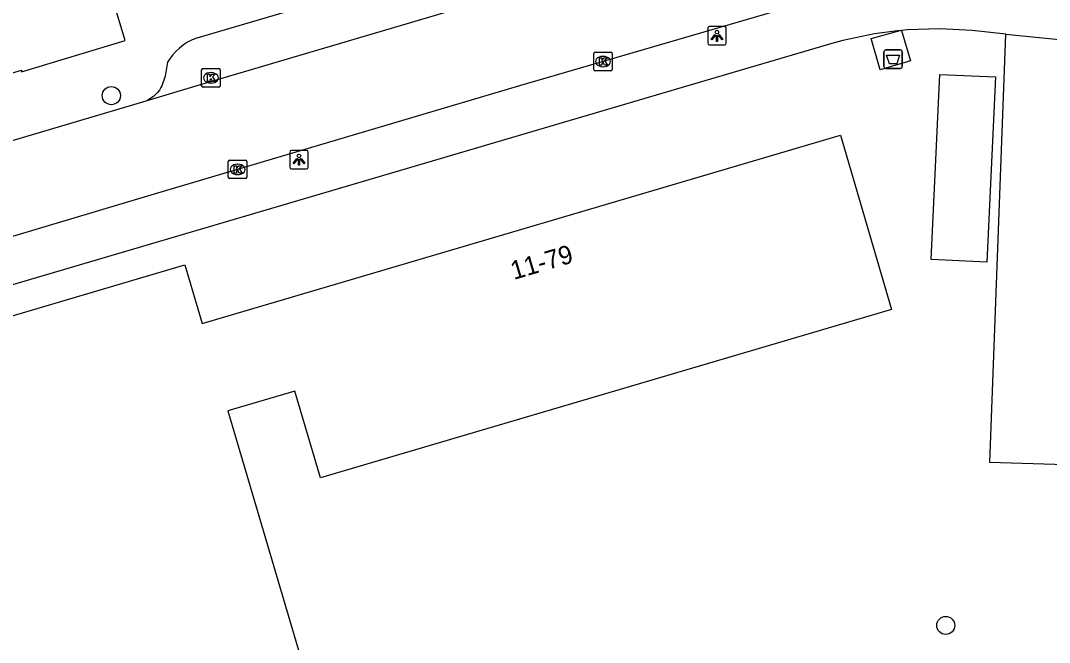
# Model space of a CAD drawing. Extents: x 161253 to 161848, y 384872 to 385383.
# Drawn here: x 161534.9 to 161590.4, y 384970 to 385003.5 of the extents above; entities that cross this region are included whole.
import ezdxf

# ---------------------------------------------------------------- set-up
doc = ezdxf.new("R2010")
doc.units = 0
for name, color, linetype in [('IMGEO_Afval_apart_plaats', 7, 'Continuous'), ('IMGEO_Boom', 7, 'Continuous'), ('IMGEO_Groenvoorziening', 7, 'Continuous'), ('IMGEO_Kolk', 7, 'Continuous'), ('IMGEO_Lichtpunt', 7, 'Continuous'), ('IMGEO_Pand', 7, 'Continuous'), ('IMGEO_Pand_nummerreeks', 7, 'Continuous'), ('IMGEO_Rijbaan_lokaal_open', 7, 'Continuous'), ('IMGEO_Voetpad_gesloten', 7, 'Continuous'), ('IMGEO_Voetpad_open', 7, 'Continuous')]:
    doc.layers.add(name, color=color, linetype=linetype)

msp = doc.modelspace()

# ---------------------------------------------------------------- linework, layer by layer
at = {"layer": 'IMGEO_Afval_apart_plaats'}
for p, q in [((161581.486, 385001.045), (161581.486, 385001.845)), ((161581.486, 385001.845), (161581.486, 385001.045)), ((161581.586, 385001.945), (161582.376, 385001.945)), ((161582.376, 385001.945), (161581.586, 385001.945)), ((161582.476, 385001.845), (161582.476, 385001.045)), ((161582.476, 385001.045), (161582.476, 385001.845)), ((161582.376, 385000.945), (161581.586, 385000.945)), ((161581.586, 385000.945), (161582.376, 385000.945))]:
    msp.add_line(p, q, dxfattribs=at)
msp.add_lwpolyline([(161581.629, 385001.659), (161582.333, 385001.659), (161582.184, 385001.189), (161581.778, 385001.189), (161581.629, 385001.659)], dxfattribs=at)
for centre, start, end in [((161581.586, 385001.845), 90, 180), ((161581.586, 385001.845), 90, 180), ((161582.376, 385001.845), 0, 90), ((161582.376, 385001.845), 360, 90), ((161581.586, 385001.045), 180, 270), ((161581.586, 385001.045), 180, 270), ((161582.376, 385001.045), 270, 0), ((161582.376, 385001.045), 270, 0)]:
    msp.add_arc(centre, 0.1, start, end, dxfattribs=at)
at = {"layer": 'IMGEO_Boom'}
for centre in [(161539.785, 384999.476), (161584.823, 384970.871)]:
    msp.add_circle(centre, 0.489, dxfattribs=at)
at = {"layer": 'IMGEO_Groenvoorziening'}
msp.add_lwpolyline([(161592.462, 384979.511), (161587.199, 384979.67), (161588.066, 385002.802)], dxfattribs=at)
at = {"layer": 'IMGEO_Kolk'}
for p, q in [((161565.894, 385001.819), (161566.746, 385001.819)), ((161565.819, 385000.893), (161565.819, 385001.745)), ((161566.307, 385001.599), (161566.332, 385001.599)), ((161566.82, 385001.745), (161566.82, 385000.893)), ((161544.659, 385000.012), (161544.659, 385000.864)), ((161544.734, 385000.938), (161545.586, 385000.938)), ((161545.147, 385000.718), (161545.172, 385000.718)), ((161545.66, 385000.864), (161545.66, 385000.012)), ((161566.746, 385000.819), (161565.894, 385000.819)), ((161566.33, 385001.039), (161566.305, 385001.039)), ((161545.17, 385000.158), (161545.145, 385000.158)), ((161545.586, 384999.938), (161544.734, 384999.938)), ((161546.099, 384995.069), (161546.099, 384995.921)), ((161546.174, 384995.995), (161547.026, 384995.995)), ((161546.587, 384995.775), (161546.612, 384995.775)), ((161547.1, 384995.921), (161547.1, 384995.069)), ((161546.61, 384995.215), (161546.585, 384995.215)), ((161547.026, 384994.995), (161546.174, 384994.995))]:
    msp.add_line(p, q, dxfattribs=at)
for points in [[(161565.894, 385001.819), (161566.746, 385001.819)], [(161565.819, 385000.893), (161565.819, 385001.745)], [(161566.14, 385001.519), (161566.263, 385001.519), (161566.263, 385001.368), (161566.393, 385001.519), (161566.557, 385001.519), (161566.411, 385001.368), (161566.564, 385001.119), (161566.412, 385001.119), (161566.327, 385001.283), (161566.263, 385001.216), (161566.263, 385001.119), (161566.14, 385001.119), (161566.14, 385001.519)], [(161566.82, 385001.745), (161566.82, 385000.893)], [(161544.659, 385000.012), (161544.659, 385000.864)], [(161544.734, 385000.938), (161545.586, 385000.938)], [(161545.66, 385000.864), (161545.66, 385000.012)], [(161566.746, 385000.819), (161565.894, 385000.819)], [(161544.98, 385000.638), (161545.103, 385000.638), (161545.103, 385000.487), (161545.233, 385000.638), (161545.397, 385000.638), (161545.251, 385000.487), (161545.404, 385000.238), (161545.252, 385000.238), (161545.167, 385000.402), (161545.103, 385000.335), (161545.103, 385000.238), (161544.98, 385000.238), (161544.98, 385000.638)], [(161545.586, 384999.938), (161544.734, 384999.938)], [(161546.099, 384995.069), (161546.099, 384995.921)], [(161546.174, 384995.995), (161547.026, 384995.995)], [(161546.42, 384995.695), (161546.543, 384995.695), (161546.543, 384995.544), (161546.673, 384995.695), (161546.837, 384995.695), (161546.691, 384995.544), (161546.844, 384995.295), (161546.692, 384995.295), (161546.607, 384995.459), (161546.543, 384995.392), (161546.543, 384995.295), (161546.42, 384995.295), (161546.42, 384995.695)], [(161547.1, 384995.921), (161547.1, 384995.069)], [(161547.026, 384994.995), (161546.174, 384994.995)]]:
    msp.add_lwpolyline(points, dxfattribs=at)
for centre, start, end in [((161565.896, 385001.743), 91.552, 178.448), ((161565.896, 385001.743), 91.552, 178.448), ((161566.744, 385001.743), 1.552, 88.448), ((161566.744, 385001.743), 1.552, 88.448), ((161544.736, 385000.862), 91.552, 178.448), ((161544.736, 385000.862), 91.552, 178.448), ((161545.584, 385000.862), 1.552, 88.448), ((161545.584, 385000.862), 1.552, 88.448), ((161565.896, 385000.895), 181.552, 268.448), ((161565.896, 385000.895), 181.552, 268.448), ((161566.744, 385000.895), 271.552, 358.448), ((161566.744, 385000.895), 271.552, 358.448), ((161544.736, 385000.014), 181.552, 268.448), ((161544.736, 385000.014), 181.552, 268.448), ((161545.584, 385000.014), 271.552, 358.448), ((161545.584, 385000.014), 271.552, 358.448), ((161546.176, 384995.919), 91.552, 178.448), ((161546.176, 384995.919), 91.552, 178.448), ((161547.024, 384995.919), 1.552, 88.448), ((161547.024, 384995.919), 1.552, 88.448), ((161546.176, 384995.071), 181.552, 268.448), ((161546.176, 384995.071), 181.552, 268.448), ((161547.024, 384995.071), 271.552, 358.448), ((161547.024, 384995.071), 271.552, 358.448)]:
    msp.add_arc(centre, 0.0765, start, end, dxfattribs=at)
for centre, major_axis, ratio, start_param, end_param in [((161566.306, 385001.319), (-0.387, 0.002), 0.722429, 4.712389, 7.853982), ((161566.331, 385001.319), (-0.39, 0.002), 0.717154, 1.570796, 4.712389), ((161545.146, 385000.438), (-0.387, 0.002), 0.722429, 4.712389, 7.853982), ((161545.171, 385000.438), (-0.39, 0.002), 0.717154, 1.570796, 4.712389), ((161546.586, 384995.495), (-0.387, 0.002), 0.722429, 4.712389, 7.853982), ((161546.611, 384995.495), (-0.39, 0.002), 0.717154, 1.570796, 4.712389)]:
    msp.add_ellipse(centre, major_axis=major_axis, ratio=ratio, start_param=start_param, end_param=end_param, dxfattribs=at)
at = {"layer": 'IMGEO_Lichtpunt'}
for p, q in [((161571.977, 385003.113), (161571.977, 385002.306)), ((161571.977, 385003.113), (161571.977, 385002.306)), ((161572.879, 385003.208), (161572.071, 385003.208)), ((161572.879, 385003.208), (161572.071, 385003.208)), ((161572.973, 385002.306), (161572.973, 385003.113)), ((161572.973, 385002.306), (161572.973, 385003.113)), ((161572.071, 385002.212), (161572.879, 385002.212)), ((161572.071, 385002.212), (161572.879, 385002.212)), ((161549.415, 384996.423), (161549.415, 384995.616)), ((161549.415, 384996.423), (161549.415, 384995.616)), ((161550.317, 384996.518), (161549.509, 384996.518)), ((161550.317, 384996.518), (161549.509, 384996.518)), ((161550.411, 384995.616), (161550.411, 384996.423)), ((161550.411, 384995.616), (161550.411, 384996.423)), ((161549.509, 384995.522), (161550.317, 384995.522)), ((161549.509, 384995.522), (161550.317, 384995.522))]:
    msp.add_line(p, q, dxfattribs=at)
for points in [[(161572.351, 385002.777), (161572.39, 385002.749), (161572.202, 385002.487), (161572.164, 385002.514), (161572.351, 385002.777)], [(161572.453, 385002.729), (161572.5, 385002.729), (161572.5, 385002.407), (161572.453, 385002.407), (161572.453, 385002.729)], [(161572.563, 385002.749), (161572.601, 385002.776), (161572.788, 385002.514), (161572.749, 385002.486), (161572.563, 385002.749)], [(161549.789, 384996.087), (161549.828, 384996.059), (161549.64, 384995.797), (161549.602, 384995.824), (161549.789, 384996.087)], [(161549.891, 384996.039), (161549.938, 384996.039), (161549.938, 384995.717), (161549.891, 384995.717), (161549.891, 384996.039)], [(161550.001, 384996.059), (161550.039, 384996.086), (161550.226, 384995.824), (161550.187, 384995.796), (161550.001, 384996.059)]]:
    msp.add_lwpolyline(points, dxfattribs=at)
for centre in [(161572.476, 385002.911), (161549.914, 384996.221)]:
    msp.add_circle(centre, 0.0994, dxfattribs=at)
for centre, start, end in [((161572.071, 385003.113), 90, 180), ((161572.071, 385003.113), 90, 180), ((161572.879, 385003.113), 0, 90), ((161572.879, 385003.113), 0, 90), ((161572.071, 385002.306), 180, 270), ((161572.071, 385002.306), 180, 270), ((161572.879, 385002.306), 270, 0), ((161572.879, 385002.306), 270, 360), ((161549.509, 384996.423), 90, 180), ((161549.509, 384996.423), 90, 180), ((161550.317, 384996.423), 0, 90), ((161550.317, 384996.423), 0, 90), ((161549.509, 384995.616), 180, 270), ((161549.509, 384995.616), 180, 270), ((161550.317, 384995.616), 270, 0), ((161550.317, 384995.616), 270, 360)]:
    msp.add_arc(centre, 0.0946, start, end, dxfattribs=at)
at = {"layer": 'IMGEO_Pand'}
for points in [[(161584.04, 384990.634), (161584.501, 385000.625), (161587.502, 385000.491), (161587.049, 384990.486), (161584.04, 384990.634)], [(161551.077, 384978.837), (161549.692, 384983.529), (161546.066, 384982.466), (161554.584, 384953.632), (161537.526, 384948.588), (161526.699, 384985.306), (161543.744, 384990.345), (161544.689, 384987.166), (161579.135, 384997.334), (161581.889, 384987.932), (161551.077, 384978.837)]]:
    msp.add_lwpolyline(points, dxfattribs=at)
at = {"layer": 'IMGEO_Rijbaan_lokaal_open'}
for points in [[(161576.83, 385009.603), (161544.407, 385000), (161541.648, 384999.183)], [(161644.123, 384999.737), (161641.51, 385000), (161585.261, 385005.661), (161583.856, 385005.737), (161582.451, 385005.688), (161581.055, 385005.513), (161579.681, 385005.214), (161579.302, 385005.109), (161561.812, 385000), (161542.1, 384994.163), (161525.218, 384989.124)], [(161541.648, 384999.183), (161531.372, 384996.139), (161523.482, 384993.851)]]:
    msp.add_lwpolyline(points, dxfattribs=at)
at = {"layer": 'IMGEO_Voetpad_gesloten'}
for points in [[(161582.44, 385002.997), (161582.926, 385001.35), (161581.281, 385000.863), (161580.806, 385002.554), (161582.364, 385002.988)], [(161582.364, 385002.988), (161582.437, 385003.008), (161582.44, 385002.997)]]:
    msp.add_lwpolyline(points, dxfattribs=at)
at = {"layer": 'IMGEO_Voetpad_open'}
for points in [[(161560.505, 385007.334), (161544.393, 385002.586), (161544.143, 385002.483), (161543.902, 385002.358), (161543.674, 385002.212), (161543.46, 385002.046), (161543.262, 385001.861), (161543.08, 385001.66), (161542.918, 385001.443), (161542.821, 385001.292), (161542.683, 385000.524), (161542.514, 385000), (161542.464, 384999.909), (161542.378, 384999.776), (161542.28, 384999.651), (161542.171, 384999.536), (161542.053, 384999.43), (161541.925, 384999.336), (161541.79, 384999.253), (161541.648, 384999.183)], [(161521.224, 384996.76), (161532.085, 385000), (161534.931, 385000.849), (161534.935, 385000.758), (161540.533, 385002.46), (161539.957, 385004.357)], [(161582.364, 385002.988), (161580.985, 385002.819), (161579.262, 385002.45), (161578.675, 385002.287), (161570.906, 385000), (161530.284, 384988.042), (161526.38, 384986.893)], [(161588.066, 385002.802), (161586.255, 385002.988), (161584.496, 385003.089), (161582.734, 385003.033), (161582.44, 385002.997)], [(161588.066, 385002.802), (161593.647, 385002.23)]]:
    msp.add_lwpolyline(points, dxfattribs=at)

# ---------------------------------------------------------------- texts
at = {"layer": 'IMGEO_Pand_nummerreeks'}
msp.add_text('11-79', height=1, rotation=16.4439, dxfattribs=at).set_placement((161561.508, 384989.524))

doc.saveas('drawing.dxf')
